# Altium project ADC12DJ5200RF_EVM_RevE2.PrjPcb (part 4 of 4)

## Sheet Power2_RevE2.SchDoc: EVM Power
size 431 x 279 mm; Date: Not shown in title block; ApprovedBy: Not shown in title block; CheckedBy: Not shown in title block; Author: Not shown in title block; CompanyName: Not shown in title block; DrawnBy: DWG; Engineer: DWG; Organization: Not shown in title block; Address1: Not shown in title block; Address2: Not shown in title block; Address3: Not shown in title block; Address4: Not shown in title block; DocumentNumber: 13; Revision: Use project parameter SCH_Rev; SheetNumber: 13; SheetTotal: 15; PageSetup: Record=PageOptions¦CenterHorizontal=True¦CenterVertical=True¦PrintScale=1.00¦XCorrection=1.00¦YCorrection=1.00¦PrintKind=0¦BorderSize=5000000¦LeftOffset=0¦BottomOffset=0¦Orientation=2¦PaperLength=1000¦PaperWidth=1000¦Scale=100¦PaperSource=15¦PrintQuality=600¦MediaType=1¦DitherType=10¦PaperKind=Letter¦PrintScaleMode=1
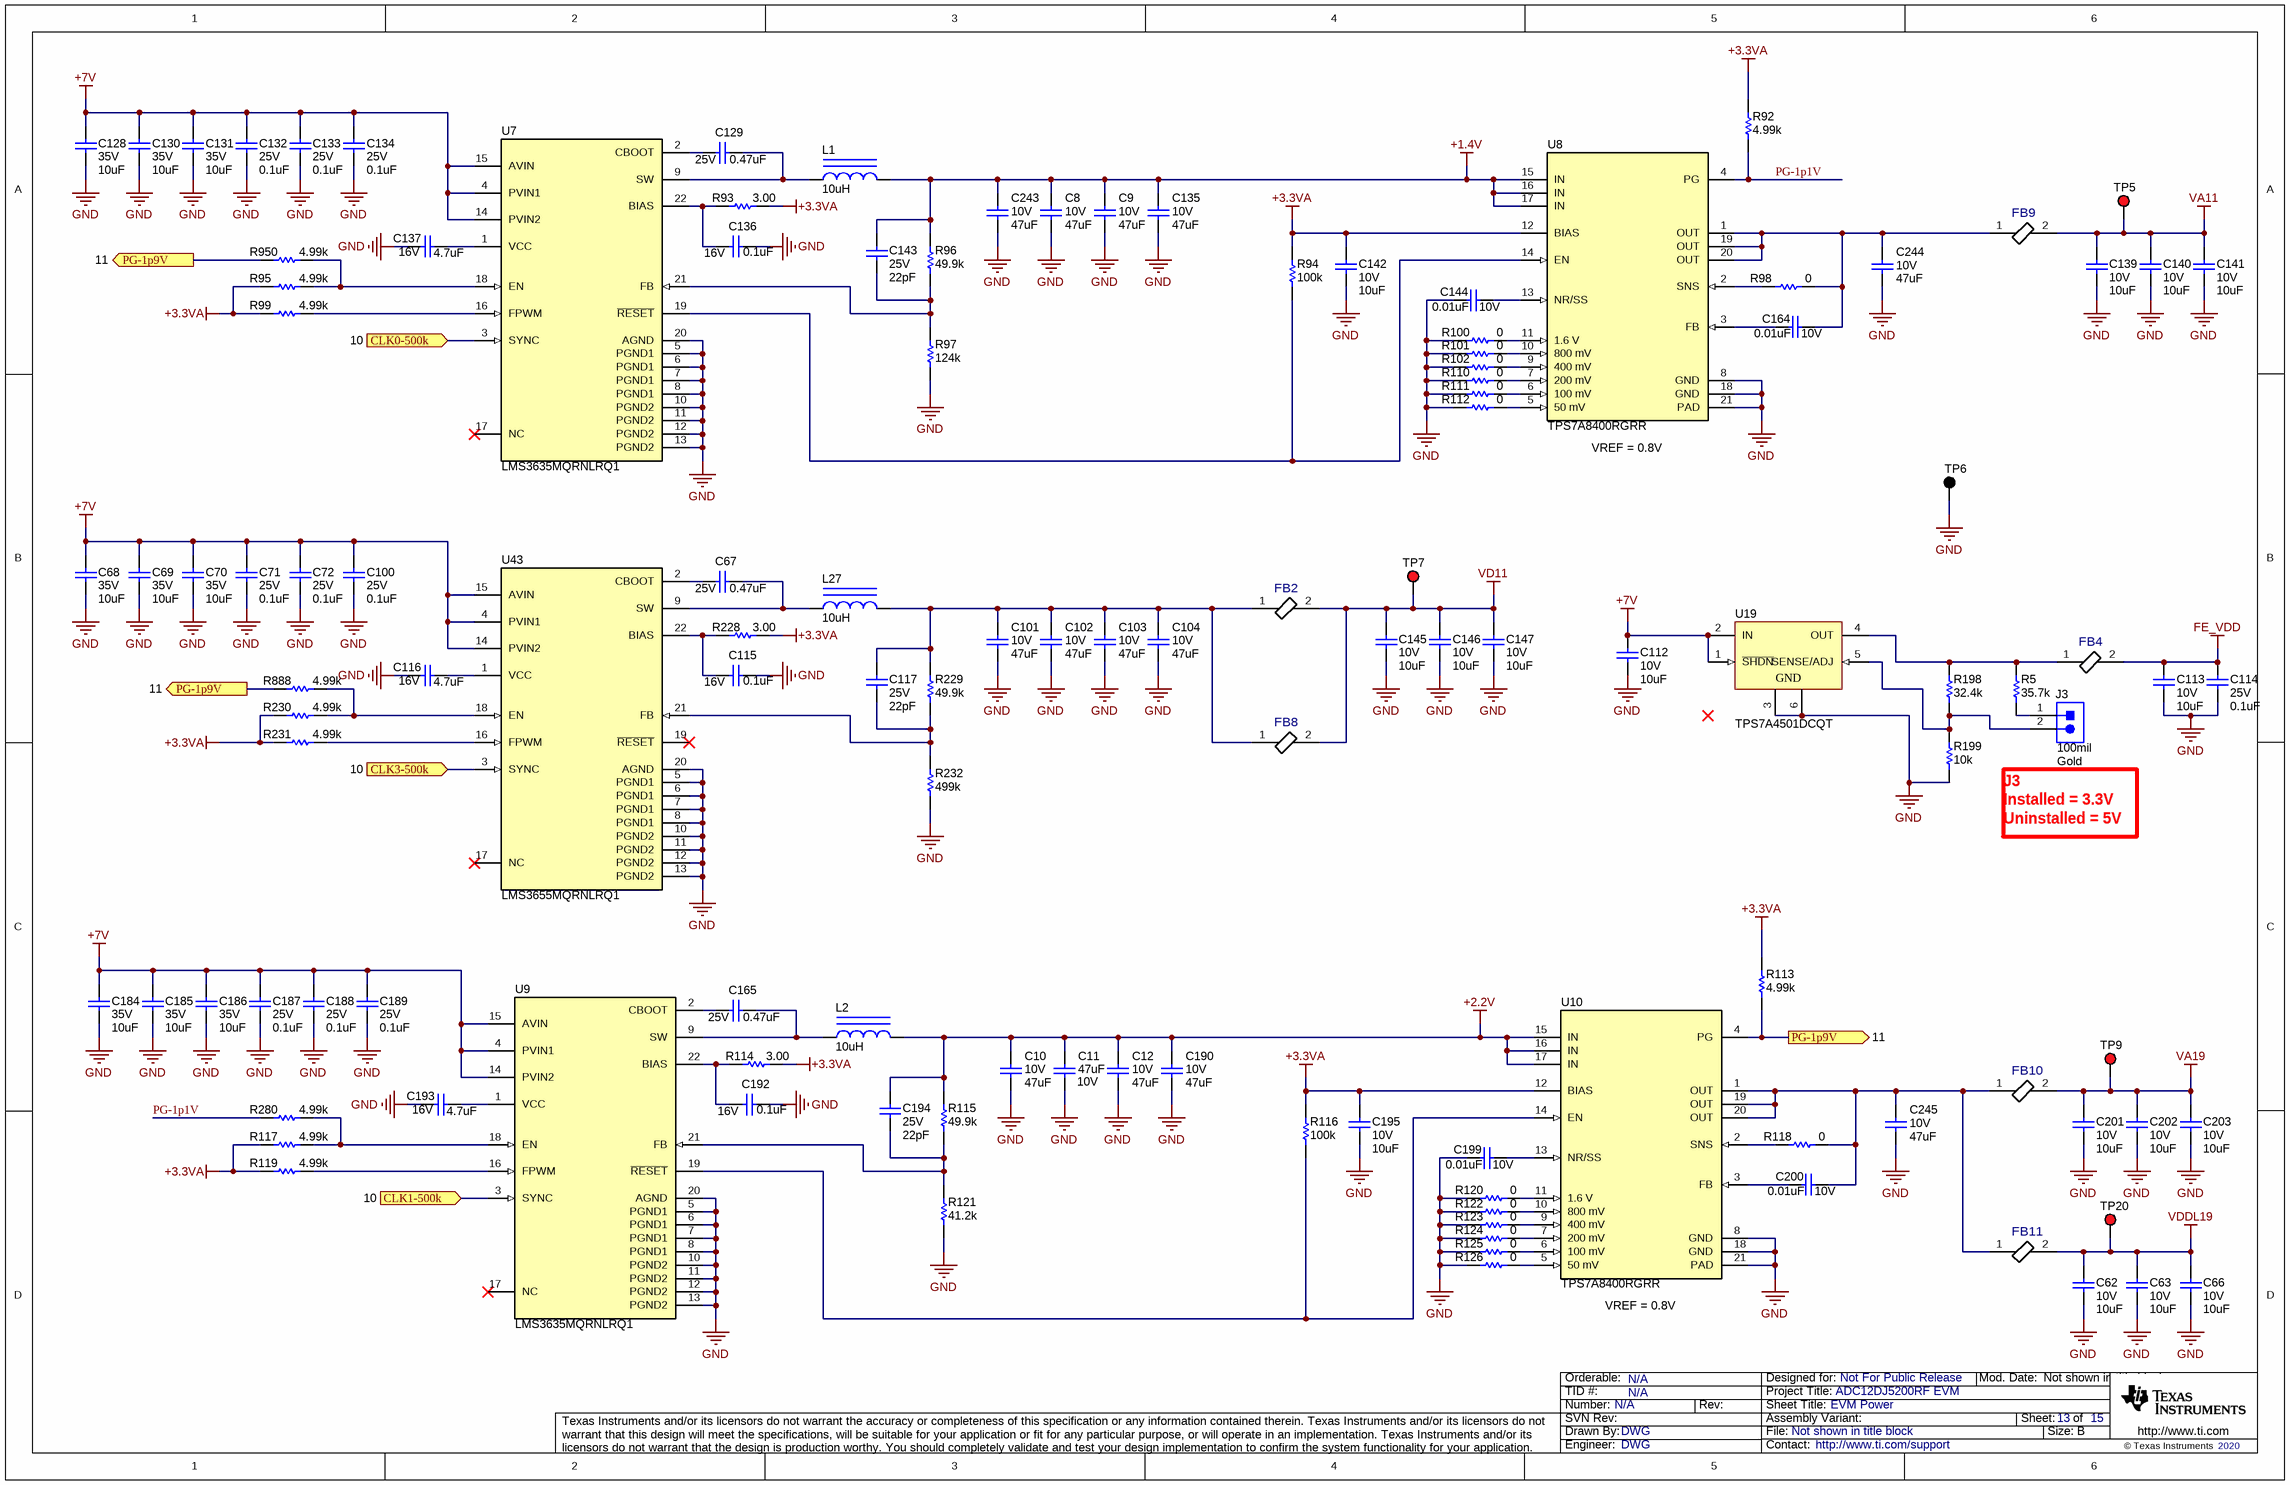
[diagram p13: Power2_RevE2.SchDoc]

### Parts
C8  VDC_V: 10V  ValueDisplayed: 47uF  [1210_270]  (hidden comment: GRM32ER71A476KE15L)
C9  VDC_V: 10V  ValueDisplayed: 47uF  [1210_270]  (hidden comment: GRM32ER71A476KE15L)
C10  VDC_V: 10V  ValueDisplayed: 47uF  [1210_270]  (hidden comment: GRM32ER71A476KE15L)
C11  VDC_V: 10V  ValueDisplayed: 47uF  [1210_270]  (hidden comment: GRM32ER71A476KE15L)
C12  VDC_V: 10V  ValueDisplayed: 47uF  [1210_270]  (hidden comment: GRM32ER71A476KE15L)
C62  VDC_V: 10V  ValueDisplayed: 10uF  [0603]  (hidden comment: GRM188Z71A106MA73D)
C63  VDC_V: 10V  ValueDisplayed: 10uF  [0603]  (hidden comment: GRM188Z71A106MA73D)
C66  VDC_V: 10V  ValueDisplayed: 10uF  [0603]  (hidden comment: GRM188Z71A106MA73D)
C67  VDC_V: 25V  ValueDisplayed: 0.47uF  [0603]  (hidden comment: GRM188R71E474KA12D)
C68  VDC_V: 35V  ValueDisplayed: 10uF  [1206_180]  (hidden comment: C3216X7R1V106K160AC)
C69  VDC_V: 35V  ValueDisplayed: 10uF  [1206_180]  (hidden comment: C3216X7R1V106K160AC)
C70  VDC_V: 35V  ValueDisplayed: 10uF  [1206_180]  (hidden comment: C3216X7R1V106K160AC)
C71  VDC_V: 25V  ValueDisplayed: 0.1uF  [0603]  (hidden comment: C1608X7R1E104K080AA)
C72  VDC_V: 25V  ValueDisplayed: 0.1uF  [0603]  (hidden comment: C1608X7R1E104K080AA)
C100  VDC_V: 25V  ValueDisplayed: 0.1uF  [0603]  (hidden comment: C1608X7R1E104K080AA)
C101  VDC_V: 10V  ValueDisplayed: 47uF  [1210_270]  (hidden comment: GRM32ER71A476KE15L)
C102  VDC_V: 10V  ValueDisplayed: 47uF  [1210_270]  (hidden comment: GRM32ER71A476KE15L)
C103  VDC_V: 10V  ValueDisplayed: 47uF  [1210_270]  (hidden comment: GRM32ER71A476KE15L)
C104  VDC_V: 10V  ValueDisplayed: 47uF  [1210_270]  (hidden comment: GRM32ER71A476KE15L)
C112  VDC_V: 10V  ValueDisplayed: 10uF  [0603]  (hidden comment: GRM188Z71A106MA73D)
C113  VDC_V: 10V  ValueDisplayed: 10uF  [0603]  (hidden comment: GRM188Z71A106MA73D)
C114  VDC_V: 25V  ValueDisplayed: 0.1uF  [0603]  (hidden comment: C1608X7R1E104K080AA)
C115  VDC_V: 16V  ValueDisplayed: 0.1uF  [0201]  (hidden comment: GRM033Z71C104KE14D)
C116  VDC_V: 16V  ValueDisplayed: 4.7uF  [0603]  (hidden comment: GRM188Z71C475KE21D)
C117  VDC_V: 25V  ValueDisplayed: 22pF  [0201_033]  (hidden comment: GCM0335C1E220JD03D)
C128  VDC_V: 35V  ValueDisplayed: 10uF  [1206_180]  (hidden comment: C3216X7R1V106K160AC)
C129  VDC_V: 25V  ValueDisplayed: 0.47uF  [0603]  (hidden comment: GRM188R71E474KA12D)
C130  VDC_V: 35V  ValueDisplayed: 10uF  [1206_180]  (hidden comment: C3216X7R1V106K160AC)
C131  VDC_V: 35V  ValueDisplayed: 10uF  [1206_180]  (hidden comment: C3216X7R1V106K160AC)
C132  VDC_V: 25V  ValueDisplayed: 0.1uF  [0603]  (hidden comment: C1608X7R1E104K080AA)
C133  VDC_V: 25V  ValueDisplayed: 0.1uF  [0603]  (hidden comment: C1608X7R1E104K080AA)
C134  VDC_V: 25V  ValueDisplayed: 0.1uF  [0603]  (hidden comment: C1608X7R1E104K080AA)
C135  VDC_V: 10V  ValueDisplayed: 47uF  [1210_270]  (hidden comment: GRM32ER71A476KE15L)
C136  VDC_V: 16V  ValueDisplayed: 0.1uF  [0201]  (hidden comment: GRM033Z71C104KE14D)
C137  VDC_V: 16V  ValueDisplayed: 4.7uF  [0603]  (hidden comment: GRM188Z71C475KE21D)
C139  VDC_V: 10V  ValueDisplayed: 10uF  [0603]  (hidden comment: GRM188Z71A106MA73D)
C140  VDC_V: 10V  ValueDisplayed: 10uF  [0603]  (hidden comment: GRM188Z71A106MA73D)
C141  VDC_V: 10V  ValueDisplayed: 10uF  [0603]  (hidden comment: GRM188Z71A106MA73D)
C142  VDC_V: 10V  ValueDisplayed: 10uF  [0603]  (hidden comment: GRM188Z71A106MA73D)
C143  VDC_V: 25V  ValueDisplayed: 22pF  [0201_033]  (hidden comment: GCM0335C1E220JD03D)
C144  VDC_V: 10V  ValueDisplayed: 0.01uF  [0201]  (hidden comment: GRM033R71A103KA01D)
C145  VDC_V: 10V  ValueDisplayed: 10uF  [0603]  (hidden comment: GRM188Z71A106MA73D)
C146  VDC_V: 10V  ValueDisplayed: 10uF  [0603]  (hidden comment: GRM188Z71A106MA73D)
C147  VDC_V: 10V  ValueDisplayed: 10uF  [0603]  (hidden comment: GRM188Z71A106MA73D)
C164  VDC_V: 10V  ValueDisplayed: 0.01uF  [0201]  (hidden comment: GRM033R71A103KA01D)
C165  VDC_V: 25V  ValueDisplayed: 0.47uF  [0603]  (hidden comment: GRM188R71E474KA12D)
C184  VDC_V: 35V  ValueDisplayed: 10uF  [1206_180]  (hidden comment: C3216X7R1V106K160AC)
C185  VDC_V: 35V  ValueDisplayed: 10uF  [1206_180]  (hidden comment: C3216X7R1V106K160AC)
C186  VDC_V: 35V  ValueDisplayed: 10uF  [1206_180]  (hidden comment: C3216X7R1V106K160AC)
C187  VDC_V: 25V  ValueDisplayed: 0.1uF  [0603]  (hidden comment: C1608X7R1E104K080AA)
C188  VDC_V: 25V  ValueDisplayed: 0.1uF  [0603]  (hidden comment: C1608X7R1E104K080AA)
C189  VDC_V: 25V  ValueDisplayed: 0.1uF  [0603]  (hidden comment: C1608X7R1E104K080AA)
C190  VDC_V: 10V  ValueDisplayed: 47uF  [1210_270]  (hidden comment: GRM32ER71A476KE15L)
C192  VDC_V: 16V  ValueDisplayed: 0.1uF  [0201]  (hidden comment: GRM033Z71C104KE14D)
C193  VDC_V: 16V  ValueDisplayed: 4.7uF  [0603]  (hidden comment: GRM188Z71C475KE21D)
C194  VDC_V: 25V  ValueDisplayed: 22pF  [0201_033]  (hidden comment: GCM0335C1E220JD03D)
C195  VDC_V: 10V  ValueDisplayed: 10uF  [0603]  (hidden comment: GRM188Z71A106MA73D)
C199  VDC_V: 10V  ValueDisplayed: 0.01uF  [0201]  (hidden comment: GRM033R71A103KA01D)
C200  VDC_V: 10V  ValueDisplayed: 0.01uF  [0201]  (hidden comment: GRM033R71A103KA01D)
C201  VDC_V: 10V  ValueDisplayed: 10uF  [0603]  (hidden comment: GRM188Z71A106MA73D)
C202  VDC_V: 10V  ValueDisplayed: 10uF  [0603]  (hidden comment: GRM188Z71A106MA73D)
C203  VDC_V: 10V  ValueDisplayed: 10uF  [0603]  (hidden comment: GRM188Z71A106MA73D)
C243  VDC_V: 10V  ValueDisplayed: 47uF  [1210_270]  (hidden comment: GRM32ER71A476KE15L)
C244  VDC_V: 10V  ValueDisplayed: 47uF  [1210_270]  (hidden comment: GRM32ER71A476KE15L)
C245  VDC_V: 10V  ValueDisplayed: 47uF  [1210_270]  (hidden comment: GRM32ER71A476KE15L)
FB2  BLM21SN300SN1D  [FP-BLM21SN300SN1D_0805-MFG]  (value not drawn)
FB4  BLM21SN300SN1D  [FP-BLM21SN300SN1D_0805-MFG]  (value not drawn)
FB8  BLM21SN300SN1D  [FP-BLM21SN300SN1D_0805-MFG]  (value not drawn)
FB9  BLM21SN300SN1D  [FP-BLM21SN300SN1D_0805-MFG]  (value not drawn)
FB10  BLM21SN300SN1D  [FP-BLM21SN300SN1D_0805-MFG]  (value not drawn)
FB11  BLM21SN300SN1D  [FP-BLM21SN300SN1D_0805-MFG]  (value not drawn)
J3  Pitch_mm: 100mil  ContactFinish: Gold  [Molex_0022284023]  (hidden comment: 3p3V)
L1  ValueDisplayed: 10uH  [XAL8080]  (hidden comment: XAL8080-103MEB)
L2  ValueDisplayed: 10uH  [XAL8080]  (hidden comment: XAL8080-103MEB)
L27  ValueDisplayed: 10uH  [XAL8080]  (hidden comment: XAL8080-103MEB)
R5  ValueDisplayed: 35.7k  [0603]  (hidden comment: RC0603FR-0735K7L)
R92  ValueDisplayed: 4.99k  [0201]  (hidden comment: RC0201FS-7D4K99L)
R93  ValueDisplayed: 3.00  [0201]  (hidden comment: RC0201FR-073RL)
R94  ValueDisplayed: 100k  [0201]  (hidden comment: RC0201FS-7D4K99L)
R95  ValueDisplayed: 4.99k  [0201]  (hidden comment: RC0201FS-7D4K99L)
R96  ValueDisplayed: 49.9k  [0201]  (hidden comment: RC0201FR-7D49K9L)
R97  ValueDisplayed: 124k  [0201]  (hidden comment: RC0201FR-7D124KL)
R98  ValueDisplayed: 0  [0201]  (hidden comment: CRCW02010000Z0ED)
R99  ValueDisplayed: 4.99k  [0201]  (hidden comment: RC0201FS-7D4K99L)
R100  ValueDisplayed: 0  [0201]  (hidden comment: CRCW02010000Z0ED)
R101  ValueDisplayed: 0  [0201]  (hidden comment: CRCW02010000Z0ED)
R102  ValueDisplayed: 0  [0201]  (hidden comment: CRCW02010000Z0ED)
R110  ValueDisplayed: 0  [0201]  (hidden comment: CRCW02010000Z0ED)
R111  ValueDisplayed: 0  [0201]  (hidden comment: CRCW02010000Z0ED)
R112  ValueDisplayed: 0  [0201]  (hidden comment: CRCW02010000Z0ED)
R113  ValueDisplayed: 4.99k  [0201]  (hidden comment: RC0201FS-7D4K99L)
R114  ValueDisplayed: 3.00  [0201]  (hidden comment: RC0201FR-073RL)
R115  ValueDisplayed: 49.9k  [0201]  (hidden comment: RC0201FR-7D49K9L)
R116  ValueDisplayed: 100k  [0201]  (hidden comment: RC0201FS-7D4K99L)
R117  ValueDisplayed: 4.99k  [0201]  (hidden comment: RC0201FS-7D4K99L)
R118  ValueDisplayed: 0  [0201]  (hidden comment: CRCW02010000Z0ED)
R119  ValueDisplayed: 4.99k  [0201]  (hidden comment: RC0201FS-7D4K99L)
R120  ValueDisplayed: 0  [0201]  (hidden comment: CRCW02010000Z0ED)
R121  ValueDisplayed: 41.2k  [0201]  (hidden comment: RC0201FR-0741K2L)
R122  ValueDisplayed: 0  [0201]  (hidden comment: CRCW02010000Z0ED)
R123  ValueDisplayed: 0  [0201]  (hidden comment: CRCW02010000Z0ED)
R124  ValueDisplayed: 0  [0201]  (hidden comment: CRCW02010000Z0ED)
R125  ValueDisplayed: 0  [0201]  (hidden comment: CRCW02010000Z0ED)
R126  ValueDisplayed: 0  [0201]  (hidden comment: CRCW02010000Z0ED)
R198  ValueDisplayed: 32.4k  [0603]  (hidden comment: RC0603FR-0732K4L)
R199  ValueDisplayed: 10k  [0603]  (hidden comment: RC0603JR-0710KL)
R228  ValueDisplayed: 3.00  [0201]  (hidden comment: RC0201FR-073RL)
R229  ValueDisplayed: 49.9k  [0201]  (hidden comment: RC0201FR-7D49K9L)
R230  ValueDisplayed: 4.99k  [0201]  (hidden comment: RC0201FS-7D4K99L)
R231  ValueDisplayed: 4.99k  [0201]  (hidden comment: RC0201FS-7D4K99L)
R232  ValueDisplayed: 499k  [0201L]  (hidden comment: RC0201FR-07499KL)
R280  ValueDisplayed: 4.99k  [0201]  (hidden comment: RC0201FS-7D4K99L)
R888  ValueDisplayed: 4.99k  [0201]  (hidden comment: RC0201FS-7D4K99L)
R950  ValueDisplayed: 4.99k  [0201]  (hidden comment: RC0201FS-7D4K99L)
TP5  5000  [Keystone5000]  (value not drawn)
TP6  5001  [Keystone5001]  (value not drawn)
TP7  5000  [Keystone5000]  (value not drawn)
TP9  5000  [Keystone5000]  (value not drawn)
TP20  5000  [Keystone5000]  (value not drawn)
U7  LMS3635MQRNLRQ1  [RNL0022A]
U8  TPS7A8400RGRR  [RGR0020A]
U9  LMS3635MQRNLRQ1  [RNL0022A]
U10  TPS7A8400RGRR  [RGR0020A]
U19  TPS7A4501DCQT  [DCQ0006A_N]
U43  LMS3655MQRNLRQ1  [RNL0022A]

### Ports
CLK0-500k (in, see 10), CLK1-500k (in, see 10), CLK3-500k (in, see 10), PG-1p9V (out, see 11)

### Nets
+1.4V: C8.1 C9.1 C135.1 C143.1 C243.1 L1.2 R96.2 U8.15(IN) U8.16(IN) U8.17(IN)
+2.2V: C10.1 C11.1 C12.1 C190.1 C194.1 L2.2 R115.2 U10.15(IN) U10.16(IN) U10.17(IN)
+3.3VA: C142.1 C195.1 R92.1 R93.2 R94.1 R95.2 R99.2 R113.1 R114.2 R116.1 R117.2 R119.2 R228.2 R230.2 R231.2 U8.12(BIAS) U10.12(BIAS)
+7V: C68.1 C69.1 C70.1 C71.1 C72.1 C100.1 C112.1 C128.1 C130.1 C131.1 C132.1 C133.1 C134.1 C184.1 C185.1 C186.1 C187.1 C188.1 C189.1 U7.4(PVIN1) U7.14(PVIN2) U7.15(AVIN) U9.4(PVIN1) U9.14(PVIN2) U9.15(AVIN) U19.1(~{SHDN}) U19.2(IN) U43.4(PVIN1) U43.14(PVIN2) U43.15(AVIN)
FE_VDD: C113.1 C114.1 FB4.2
GND: C8.2 C9.2 C10.2 C11.2 C12.2 C62.2 C63.2 C66.2 C68.2 C69.2 C70.2 C71.2 C72.2 C100.2 C101.2 C102.2 C103.2 C104.2 C112.2 C113.2 C114.2 C115.1 C116.1 C128.2 C130.2 C131.2 C132.2 C133.2 C134.2 C135.2 C136.1 C137.1 C139.2 C140.2 C141.2 C142.2 C144.2 C145.2 C146.2 C147.2 C184.2 C185.2 C186.2 C187.2 C188.2 C189.2 C190.2 C192.1 C193.1 C195.2 C199.2 C201.2 C202.2 C203.2 C243.2 C244.2 C245.2 R97.1 R100.1 R101.1 R102.1 R110.1 R111.1 R112.1 R120.1 R121.1 R122.1 R123.1 R124.1 R125.1 R126.1 R199.1 R232.1 TP6.1 U7.5(PGND1) U7.6(PGND1) U7.7(PGND1) U7.8(PGND1) U7.10(PGND2) U7.11(PGND2) U7.12(PGND2) U7.13(PGND2) U7.20(AGND) U8.8(GND) U8.18(GND) U8.21(PAD) U9.5(PGND1) U9.6(PGND1) U9.7(PGND1) U9.8(PGND1) U9.10(PGND2) U9.11(PGND2) U9.12(PGND2) U9.13(PGND2) U9.20(AGND) U10.8(GND) U10.18(GND) U10.21(PAD) U19.3(GND) U19.6(GND) U43.5(PGND1) U43.6(PGND1) U43.7(PGND1) U43.8(PGND1) U43.10(PGND2) U43.11(PGND2) U43.12(PGND2) U43.13(PGND2) U43.20(AGND)
VA11: C139.1 C140.1 C141.1 FB9.2 TP5.1
VA19: C201.1 C202.1 C203.1 FB10.2 TP9.1
VD11: C145.1 C146.1 C147.1 FB2.2 FB8.2 TP7.1
VDDL19: C62.1 C63.1 C66.1 FB11.2 TP20.1
CLK0-500k: U7.3(SYNC) ; port CLK0-500k
CLK1-500k: U9.3(SYNC) ; port CLK1-500k
CLK3-500k: U43.3(SYNC) ; port CLK3-500k
PG-1p1V: R92.2 R280.2 U8.4(PG)
PG-1p9V: R113.2 R888.2 R950.2 U10.4(PG) ; port PG-1p9V
NetC67_1: C67.1 U43.2(CBOOT)
NetC67_2: C67.2 L27.1 U43.9(SW)
NetC101_1: C101.1 C102.1 C103.1 C104.1 C117.1 FB2.1 FB8.1 L27.2 R229.2
NetC115_2: C115.2 R228.1 U43.22(BIAS)
NetC116_2: C116.2 U43.1(VCC)
NetC117_2: C117.2 R229.1 R232.2 U43.21(FB)
NetC129_1: C129.1 U7.2(CBOOT)
NetC129_2: C129.2 L1.1 U7.9(SW)
NetC136_2: C136.2 R93.1 U7.22(BIAS)
NetC137_2: C137.2 U7.1(VCC)
NetC143_2: C143.2 R96.1 R97.2 U7.21(FB)
NetC144_1: C144.1 U8.13(NR/SS)
NetC164_1: C164.1 C244.1 FB9.1 R98.2 U8.1(OUT) U8.19(OUT) U8.20(OUT)
NetC164_2: C164.2 U8.3(FB)
NetC165_1: C165.1 U9.2(CBOOT)
NetC165_2: C165.2 L2.1 U9.9(SW)
NetC192_2: C192.2 R114.1 U9.22(BIAS)
NetC193_2: C193.2 U9.1(VCC)
NetC194_2: C194.2 R115.1 R121.2 U9.21(FB)
NetC199_1: C199.1 U10.13(NR/SS)
NetC200_1: C200.1 C245.1 FB10.1 FB11.1 R118.2 U10.1(OUT) U10.19(OUT) U10.20(OUT)
NetC200_2: C200.2 U10.3(FB)
NetFB4_1: FB4.1 R5.2 R198.2 U19.4(OUT)
NetJ3_1: J3.1 R5.1
NetJ3_2: J3.2 R198.1 R199.2 U19.5(SENSE/ADJ)
NetR94_2: R94.2 U7.19(~{RESET}) U8.14(EN)
NetR95_1: R95.1 R950.1 U7.18(EN)
NetR98_1: R98.1 U8.2(SNS)
NetR99_1: R99.1 U7.16(FPWM)
NetR100_2: R100.2 U8.11(1.6_V)
NetR101_2: R101.2 U8.10(800_mV)
NetR102_2: R102.2 U8.9(400_mV)
NetR110_2: R110.2 U8.7(200_mV)
NetR111_2: R111.2 U8.6(100_mV)
NetR112_2: R112.2 U8.5(50_mV)
NetR116_2: R116.2 U9.19(~{RESET}) U10.14(EN)
NetR117_1: R117.1 R280.1 U9.18(EN)
NetR118_1: R118.1 U10.2(SNS)
NetR119_1: R119.1 U9.16(FPWM)
NetR120_2: R120.2 U10.11(1.6_V)
NetR122_2: R122.2 U10.10(800_mV)
NetR123_2: R123.2 U10.9(400_mV)
NetR124_2: R124.2 U10.7(200_mV)
NetR125_2: R125.2 U10.6(100_mV)
NetR126_2: R126.2 U10.5(50_mV)
NetR230_1: R230.1 R888.1 U43.18(EN)
NetR231_1: R231.1 U43.16(FPWM)

Not connected (* = marked no-connect by the designer): U7 17(NC)*; U9 17(NC)*; U43 17(NC)* 19(~{RESET})*

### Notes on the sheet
- (near U8) VREF = 0.8V
- J3
  Installed = 3.3V
  Uninstalled = 5V
- (near U10) VREF = 0.8V

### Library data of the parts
C8-C12 C101-C104 C135 C190 C243-C245 = CMP-0009220-2: CAP, CERM, 47 uF, 10 V, +/- 10%, X7R, 1210; Manufacturer: MuRata; TaMin_C: -55°C; Polarized: N; SizeAreaWB_mm2: 14.7; Value1: Unknown; U/M: EA; Value: 47uF; TaMax_C: 125°C; SizeZ_mm: 2.7; SizeX_mm: 3.2; SizeY_mm: 2.5; Cap_Case: 1210; SizeArea_mm2: 8; Cap_F: 47µF; AEC Category: Q200
C62 C63 C66 C112 C113 C139-C142 C145-C147 C195 C201-C203 = CMP-0007497-5: CAP, CERM, 10 uF, 10 V, +/- 20%, X7R, 0603; Manufacturer: MuRata; TaMin_C: -55°C; Polarized: N; SizeAreaWB_mm2: 4.68; Value1: Unknown; U/M: EA; Value: 10uF; TaMax_C: 125°C; SizeZ_mm: 1; SizeX_mm: 1.6; SizeY_mm: 0.8; SizeArea_mm2: 1.28; Cap_F: 10µF; AEC Category: Q200
C67 C129 C165 = CMP-0007424-4: CAP, CERM, 0.47 uF, 25 V, +/- 10%, X7R, 0603; Manufacturer: MuRata; TaMin_C: -55°C; Polarized: N; SizeAreaWB_mm2: 4.68; Value1: Unknown; U/M: EA; Value: 0.47uF; TaMax_C: 125°C; SizeZ_mm: 1; SizeX_mm: 1.6; SizeY_mm: 0.8; SizeArea_mm2: 1.28; Cap_F: 470nF; AEC Category: Q200
C68-C70 C128 C130 C131 C184-C186 = CMP-0008705-2: CAP, CERM, 10 uF, 35 V, +/- 10%, X7R, 1206; Manufacturer: TDK; TaMin_C: -55°C; ESR_ohm: 2.229m; Polarized: N; SizeAreaWB_mm2: 10.92; Value1: 0.002229 ohm; U/M: EA; Value: 10uF; TaMax_C: 125°C; SizeZ_mm: 1.8; SizeX_mm: 3.2; SizeY_mm: 1.6; SizeArea_mm2: 5.12; Cap_F: 10µF; IRMS_A: 4.85932A; AEC Category: Q200
C71 C72 C100 C114 C132-C134 C187-C189 = CMP-0007039-5: CAP, CERM, 0.1 uF, 25 V, +/- 10%, X7R, 0603; Manufacturer: TDK; TaMin_C: -55°C; Polarized: N; SizeAreaWB_mm2: 4.68; Value1: Unknown; U/M: EA; Value: 0.1uF; TaMax_C: 125°C; SizeZ_mm: 1; SizeX_mm: 1.6; SizeY_mm: 0.8; SizeArea_mm2: 1.28; Cap_F: 100nF; AEC Category: Q200
C115 C136 C192 = CMP-0064970-1: CAP, CERM, 0.1 uF, 16 V,+/- 10%, X7R, 0201; Manufacturer: MuRata; TaMin_C: -55°C; Polarized: N; SizeAreaWB_mm2: 2.08; Value1: Unknown; U/M: EA; Value: 0.1uF; TaMax_C: 125°C; SizeZ_mm: 0.26; SizeX_mm: 0.6; SizeY_mm: 0.3; SizeArea_mm2: 0.18; Cap_F: 100nF; AEC Category: Q200
C116 C137 C193 = CMP-0064936-4: CAP, CERM, 4.7 uF, 16 V,+/- 10%, X7R, 0603; Manufacturer: MuRata; TaMin_C: -55°C; Polarized: N; SizeAreaWB_mm2: 4.68; Value1: Unknown; U/M: EA; Value: 4.7uF; TaMax_C: 125°C; SizeZ_mm: 1; SizeX_mm: 1.6; SizeY_mm: 0.8; SizeArea_mm2: 1.28; Cap_F: 4.7µF; AEC Category: Q200
C117 C143 C194 = CMP-0009659-3: CAP, CERM, 22 pF, 25 V, +/- 5%, C0G/NP0, AEC-Q200 Grade 1, 0201; Manufacturer: MuRata; TaMin_C: -55°C; Polarized: N; SizeAreaWB_mm2: 2.08; Value1: Unknown; U/M: EA; Value: 22pF; TaMax_C: 125°C; SizeZ_mm: 0.33; SizeX_mm: 0.6; SizeY_mm: 0.3; Cap_Case: 0201; SizeArea_mm2: 0.18; AEC Qualified: Y; AEC Grade: 1; AEC Category: Q200
C144 C164 C199 C200 = CMP-0009732-1: CAP, CERM, 0.01 uF, 10 V, +/- 10%, X7R, 0201; Manufacturer: MuRata; TaMin_C: -55°C; Polarized: N; SizeAreaWB_mm2: 2.08; Value1: Unknown; U/M: EA; Value: 0.01uF; TaMax_C: 125°C; SizeZ_mm: 0.26; SizeX_mm: 0.6; SizeY_mm: 0.3; SizeArea_mm2: 0.18; Cap_F: 10nF; AEC Category: Q200
FB2 FB4 FB8-FB11 = CMP-0081829-1: 30 Ohms @ 100MHz 1 Power Line Ferrite Bead 0805 (2012 Metric) 8.5A 4mOhm; Manufacturer: Murata; SizeZ_mm: 1.05mm; Impedance At Frequency: 30Ω @ 100MHz; Symbol Name: SYM-BLM21SN300SN1D; AEC Qualified: No; DCR_ohm: 0.004Ω
J3 = CMP-0055333-1: Header, 2.54mm, 2x1, Tin, TH; Manufacturer: Molex; PartNumber: 22284023; CNHeader: TRUE; Current_A: 4A; Shrouded: N; Gender: Male; Voltage_V: 250V; Row_Count: 1; CT: FALSE; Cert_UL: Y
L1 L2 L27 = CMP-0061060-1: Inductor, Shielded, Composite, 10 uH, 8.7 A, 0.021 ohm, SMD; Manufacturer: Coilcraft; Isat: 11A @ 30% inductance drop; Irms: 8.7A @ 40C rise; Green_Lifecycle: Not Set; SizeAreaWB_mm2: 107.06; DCR_ohm: 0.021; Green_REACh: Incomplete; Value: 10uH; Imax_A: 8.7A; SizeZ_mm: 8; SizeX_mm: 8.1; SizeY_mm: 8.6; SizeArea_mm2: 69.66; Ind_H: 10µH; AEC Qualified: N; AEC Category: Q200
R5 = CMP-0023050-5: RES, 35.7 k, 1%, 0.1 W, 0603; Manufacturer: Yageo; Power_W: 100mW; TempCo: 100 ppm/C; Value_Code: 35k7; Value: 35.7k; EIA_Code: E96; SizeX_mm: 1.6; SizeY_mm: 0.8; SizeZ_mm: 1; Value2: 0.1W; SizeArea_mm2: 1.28; AEC Qualified: N; VDC_V: 75V; AEC Category: Q200; SizeAreaWB_mm2: 4.68
R92 R95 R99 R113 R117 R119 R230 R231 R280 = CMP-0028107-1: RES, 4.99 k, 1%, 0.05 W, 0201; Manufacturer: Yageo America; Power_W: 50mW; TempCo: 200 ppm/C; Value_Code: 4k99; U/M: EA; Value: 4.99k; EIA_Code: E96; SizeX_mm: 0.6; SizeY_mm: 0.3; SizeZ_mm: 0.26; Value2: 0.05W; SizeArea_mm2: 0.18; AEC Qualified: N; VDC_V: 25V; AEC Category: Q200
R93 R114 R228 = CMP-0027685-1: RES, 3.00, 1%, 0.05 W, 0201; Manufacturer: Yageo America; Power_W: 50mW; TempCo: 350 ppm/C; Value_Code: 3R00; U/M: EA; Value: 3.00; Res_ohm: 3; SizeX_mm: 0.6; SizeY_mm: 0.3; SizeZ_mm: 0.26; Value2: 0.05W; SizeArea_mm2: 0.18; AEC Qualified: N; VDC_V: 25V; AEC Category: Q200
R94 R116 = CMP-0028069-1: RES, 100 k, 1%, 0.05 W, 0201; Manufacturer: Yageo America; PartNumber: RC0201FS-7D100KL; Power_W: 50mW; TempCo: 200 ppm/C; U/M: EA; Value: 100k; EIA_Code: E96; SizeX_mm: 0.6; SizeY_mm: 0.3; SizeZ_mm: 0.26; Value2: 0.05W; SizeArea_mm2: 0.18; CompType: Resistor; AEC Qualified: N; VDC_V: 25V; AEC Category: Q200
R96 R115 R229 = CMP-0028027-1: RES, 49.9 k, 1%, 0.05 W, 0201; Manufacturer: Yageo America; Power_W: 50mW; TempCo: 200 ppm/C; Value_Code: 49k9; U/M: EA; Value: 49.9k; EIA_Code: E96; SizeX_mm: 0.6; SizeY_mm: 0.3; SizeZ_mm: 0.26; Value2: 0.05W; SizeArea_mm2: 0.18; AEC Qualified: N; VDC_V: 25V; AEC Category: Q200
R97 = CMP-0027952-1: RES, 124 k, 1%, 0.05 W, 0201; Manufacturer: Yageo America; Power_W: 50mW; TempCo: 200 ppm/C; U/M: EA; Value: 124k; EIA_Code: E96; SizeX_mm: 0.6; SizeY_mm: 0.3; SizeZ_mm: 0.26; Value2: 0.05W; SizeArea_mm2: 0.18; AEC Qualified: N; VDC_V: 25V; AEC Category: Q200
R98 R100-R102 R110-R112 R118 R120 R122-R126 = CMP-0027008-4: RES, 0, 5%, 0.05 W, 0201; Manufacturer: Vishay-Dale; Power_W: 50mW; TempCo: ppm/C; Value_Code: 0000; Value: 0; EIA_Code: E24; SizeX_mm: 0.6; SizeY_mm: 0.3; SizeZ_mm: 0.26; Value2: 0.05W; SizeArea_mm2: 0.18; AEC Qualified: N; AEC Category: Q200
R121 = CMP-0027692-1: RES, 41.2 k, 1%, 0.05 W, 0201; Manufacturer: Yageo America; Power_W: 50mW; TempCo: 200 ppm/C; Value_Code: 41k2; U/M: EA; Value: 41.2k; EIA_Code: E96; SizeX_mm: 0.6; SizeY_mm: 0.3; SizeZ_mm: 0.26; Value2: 0.05W; SizeArea_mm2: 0.18; CompType: Resistor; AEC Qualified: N; VDC_V: 25V; AEC Category: Q200
R198 = CMP-0023030-5: RES, 32.4 k, 1%, 0.1 W, 0603; Manufacturer: Yageo; Power_W: 100mW; TempCo: 100 ppm/C; Value_Code: 32k4; Value: 32.4k; EIA_Code: E96; SizeX_mm: 1.6; SizeY_mm: 0.8; SizeZ_mm: 1; Value2: 0.1W; SizeArea_mm2: 1.28; AEC Qualified: N; VDC_V: 75V; AEC Category: Q200; SizeAreaWB_mm2: 4.68
R199 = CMP-0025886-5: RES, 10 k, 5%, 0.1 W, 0603; Manufacturer: Yageo; Power_W: 100mW; TempCo: 100 ppm/C; Value_Code: 10k0; Value: 10k; EIA_Code: E24; SizeX_mm: 1.6; SizeY_mm: 0.8; SizeZ_mm: 1; Value2: 0.1W; SizeArea_mm2: 1.28; AEC Qualified: N; VDC_V: 75V; AEC Category: Q200; SizeAreaWB_mm2: 4.68
R232 = CMP-0027730-1: RES, 499 k, 1%, 0.05 W, 0201; Manufacturer: Yageo America; Power_W: 50mW; TempCo: 200 ppm/C; U/M: EA; Value: 499k; EIA_Code: E96; SizeX_mm: 0.6; SizeY_mm: 0.3; SizeZ_mm: 0.26; Value2: 0.05W; SizeArea_mm2: 0.18; AEC Qualified: N; VDC_V: 25V; AEC Category: Q200
R888 R950 = CMP-0028107-1: RES, 4.99 k, 1%, 0.05 W, 0201; Manufacturer: Yageo America; Power_W: 50mW; TempCo: 200 ppm/C; Value_Code: 4k99; U/M: EA; Value: 4.99k; EIA_Code: E96; SizeX_mm: 0.6; SizeY_mm: 0.3; SizeZ_mm: 0.26; Value2: 0.05W; SizeArea_mm2: 0.18; CompType: Resistor; AEC Qualified: N; VDC_V: 25V; AEC Category: Q200
TP5 TP7 TP9 TP20 = CMP-0055137-1: Test Point, Miniature, Red, TH; Manufacturer: Keystone; CNHeader: FALSE; Green_Lifecycle: Active; Green_REACh: Passed; ContactFinish: Silver; CT: TRUE
TP6 = CMP-0055138-1: Test Point, Miniature, Black, TH; Manufacturer: Keystone; CNHeader: FALSE; Green_Lifecycle: Active; Green_REACh: Passed; ContactFinish: Silver; CT: TRUE
U7 U9 = CMP-0013906-5: 3.5A, 36V Synchronous, 400kHz, Step-Down Converter, RNL0022A (VQFN-HR-22); Manufacturer: Texas Instruments; Alternate PartNumber: LMS3635MQRNLTQ1; SizeX_mm: 4.0; SizeY_mm: 5.0; CompType: IC; SizeZ_mm: 0.9; SizeArea_mm2: 20.0; SizeAreaWB_mm2: 42.0; AEC Category: Q200; AEC Qualified: Y; Rating: Automotive
U8 U10 = CMP-0073871-3: High-Current (3 A), High-Accuracy (1%), Low-Noise (4.4 uVRMS), LDO Voltage Regulator, RGR0020A (VQFN-20); Alternate PartNumber: TPS7A8400RGRT; Alternate Manufacturer: Texas Instruments; Green_Lifecycle: Active; SizeAreaWB_mm2: 20.25; Green_REACh: Passed; SizeZ_mm: 1.0; SizeX_mm: 3.5; SizeArea_mm2: 12.25; CompType: IC; AEC Category: Q200; AEC Qualified: N
U19 = CMP-0036724-1: Single Output Fast Transient Response LDO, 1.5 A,Adjustable Output, 2.1 to 20 V Input, 6-pin SOT-223 (DCQ), -40 to 125 degC, Green (RoHS & no Sb/Br); Manufacturer: Texas Instruments; Vout Adj(Min)(V): 1.2; SubFamily: Single Channel LDO; Vdo(Typ)(mV): 300; Vin(Min)(V): 2.1; Accuracy(%): 1; Vin(Max)(V): 20; Vout Adj(Max)(V): 5; Iout(Max)(A): 1.5
U43 = CMP-0013911-5: 5.5A, 36V Synchronous, 400kHz, Step-Down Converter, RNL0022A (VQFN-HR-22); Manufacturer: Texas Instruments; Alternate PartNumber: LMS3655MQRNLTQ1; SizeX_mm: 4.0; SizeY_mm: 5.0; CompType: IC; SizeZ_mm: 0.9; SizeArea_mm2: 20.0; SizeAreaWB_mm2: 42.0; AEC Category: Q200; AEC Qualified: Y; Rating: Automotive

## Sheet USB_RevE2.SchDoc: USB Interface
size 431 x 279 mm; Date: Not shown in title block; ApprovedBy: Not shown in title block; CheckedBy: Not shown in title block; Author: Not shown in title block; CompanyName: Not shown in title block; DrawnBy: DWG; Engineer: Not shown in title block; Organization: Not shown in title block; Address1: Not shown in title block; Address2: Not shown in title block; Address3: Not shown in title block; Address4: Not shown in title block; DocumentNumber: 14; Revision: Use project parameter SCH_Rev; SheetNumber: 14; SheetTotal: 15; PageSetup: Record=PageOptions¦CenterHorizontal=True¦CenterVertical=True¦PrintScale=1.00¦XCorrection=1.00¦YCorrection=1.00¦PrintKind=0¦BorderSize=5000000¦LeftOffset=0¦BottomOffset=0¦Orientation=2¦PaperLength=1000¦PaperWidth=1000¦Scale=100¦PaperSource=15¦PrintQuality=600¦MediaType=1¦DitherType=10¦PaperKind=Letter¦PrintScaleMode=1
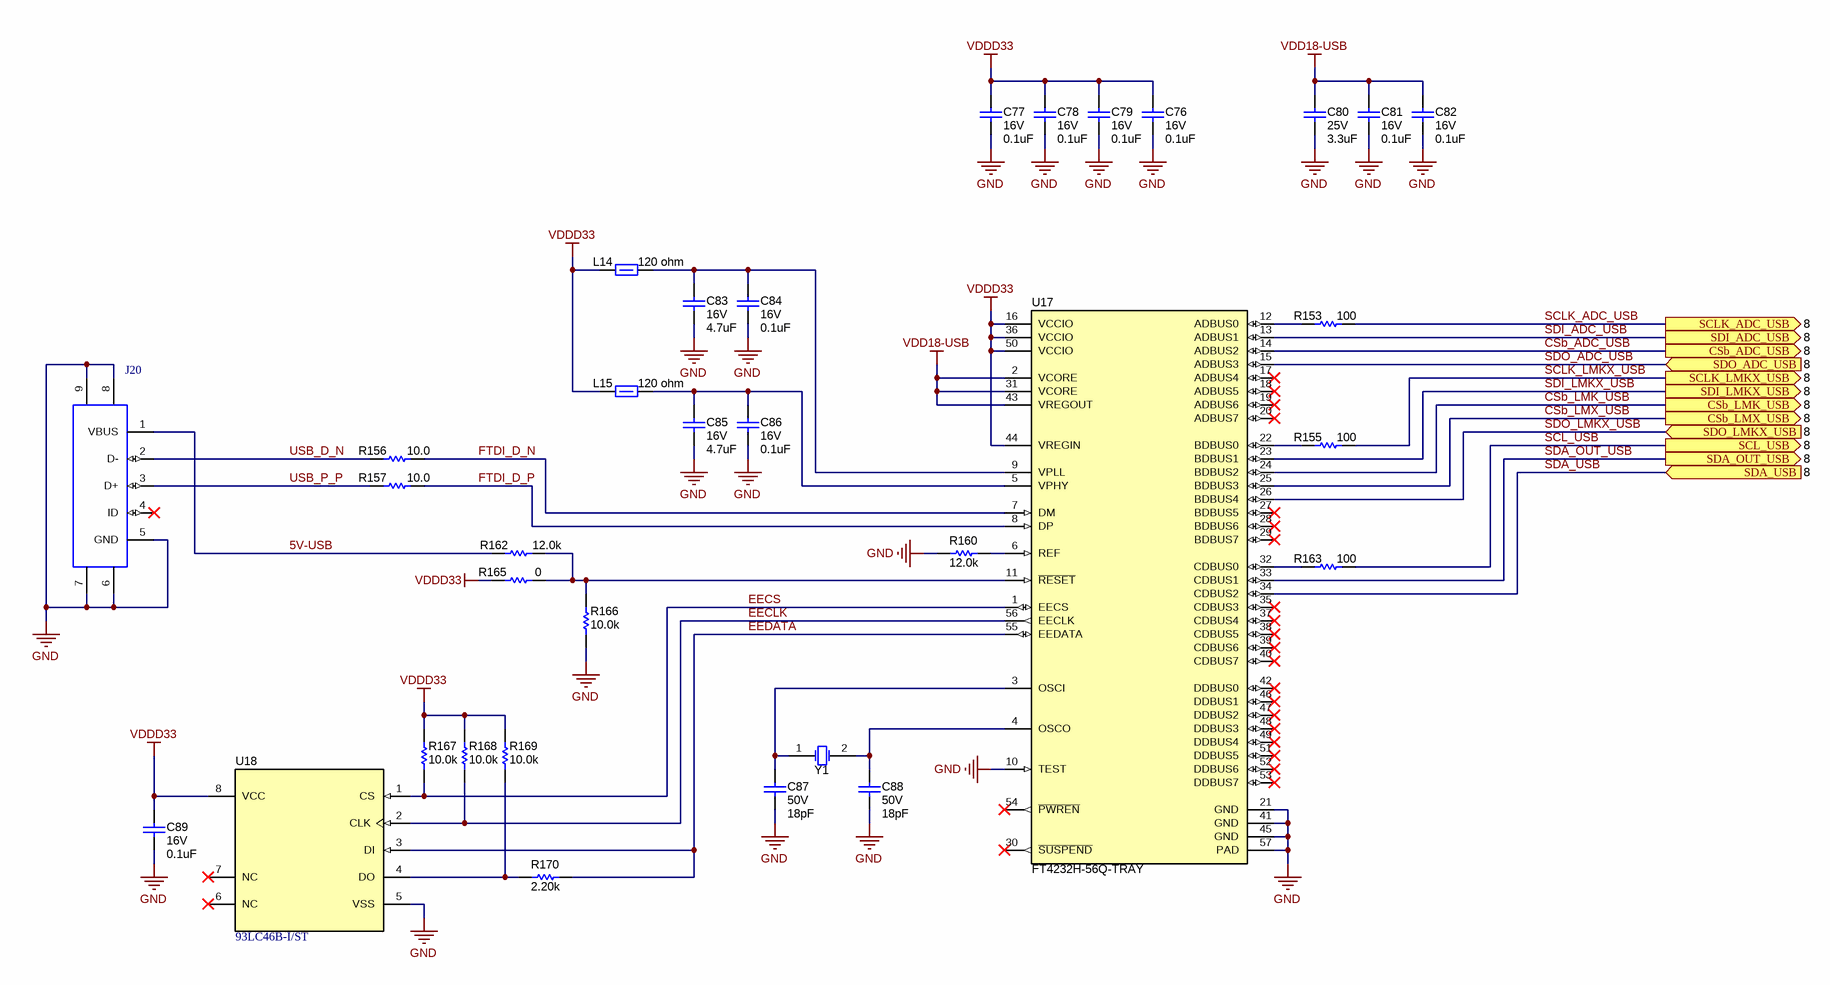
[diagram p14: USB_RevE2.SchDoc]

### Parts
C76  VDC_V: 16V  ValueDisplayed: 0.1uF  [0201L]  (hidden comment: GRM033Z71C104KE14D)
C77  VDC_V: 16V  ValueDisplayed: 0.1uF  [0201L]  (hidden comment: GRM033Z71C104KE14D)
C78  VDC_V: 16V  ValueDisplayed: 0.1uF  [0201L]  (hidden comment: GRM033Z71C104KE14D)
C79  VDC_V: 16V  ValueDisplayed: 0.1uF  [0201L]  (hidden comment: GRM033Z71C104KE14D)
C80  VDC_V: 25V  ValueDisplayed: 3.3uF  [0603]  (hidden comment: C1608X5R1E335K080AC)
C81  VDC_V: 16V  ValueDisplayed: 0.1uF  [0201L]  (hidden comment: GRM033Z71C104KE14D)
C82  VDC_V: 16V  ValueDisplayed: 0.1uF  [0201L]  (hidden comment: GRM033Z71C104KE14D)
C83  VDC_V: 16V  ValueDisplayed: 4.7uF  [0603]  (hidden comment: GRM188Z71C475KE21D)
C84  VDC_V: 16V  ValueDisplayed: 0.1uF  [0201L]  (hidden comment: GRM033Z71C104KE14D)
C85  VDC_V: 16V  ValueDisplayed: 4.7uF  [0603]  (hidden comment: GRM188Z71C475KE21D)
C86  VDC_V: 16V  ValueDisplayed: 0.1uF  [0201L]  (hidden comment: GRM033Z71C104KE14D)
C87  VDC_V: 50V  ValueDisplayed: 18pF  [0402L]  (hidden comment: C1005C0G1H180J050BA)
C88  VDC_V: 50V  ValueDisplayed: 18pF  [0402L]  (hidden comment: C1005C0G1H180J050BA)
C89  VDC_V: 16V  ValueDisplayed: 0.1uF  [0201L]  (hidden comment: GRM033Z71C104KE14D)
J20  1734035-2  [CONN_USB-Mini-B-1734035-2]  (value not drawn)
L14  ValueDisplayed: 120 ohm  [0402]  (hidden comment: 74279271)
L15  ValueDisplayed: 120 ohm  [0402]  (hidden comment: 74279271)
R153  ValueDisplayed: 100  [0201L]  (hidden comment: RC0201FR-7D100RL)
R155  ValueDisplayed: 100  [0201L]  (hidden comment: RC0201FR-7D100RL)
R156  ValueDisplayed: 10.0  [0201L]  (hidden comment: RC0201FR-7D10RL)
R157  ValueDisplayed: 10.0  [0201L]  (hidden comment: RC0201FR-7D10RL)
R160  ValueDisplayed: 12.0k  [0201L]  (hidden comment: RC0201FR-7D12KL)
R162  ValueDisplayed: 12.0k  [0201L]  (hidden comment: RC0201FR-7D12KL)
R163  ValueDisplayed: 100  [0201L]  (hidden comment: RC0201FR-7D100RL)
R165  ValueDisplayed: 0  [0201L]  (hidden comment: CRCW02010000Z0ED)
R166  ValueDisplayed: 10.0k  [0201L]  (hidden comment: RC0201FR-7D10KL)
R167  ValueDisplayed: 10.0k  [0201L]  (hidden comment: RC0201FR-7D10KL)
R168  ValueDisplayed: 10.0k  [0201L]  (hidden comment: RC0201FR-7D10KL)
R169  ValueDisplayed: 10.0k  [0201L]  (hidden comment: RC0201FR-7D10KL)
R170  ValueDisplayed: 2.20k  [0201L]  (hidden comment: RC0201FR-7D2K2L)
U17  FT4232H-56Q-TRAY  [VQFN-56]
U18  93LC46B-I/ST  [TSSOP-8]
Y1  ABM3-12.000MHZ-D2Y-T  [XTAL_ABM3]  (value not drawn)

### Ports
CSb_ADC_USB (out, see 8), CSb_LMK_USB (out, see 8), CSb_LMX_USB (out, see 8), SCL_USB (out, see 8), SCLK_ADC_USB (out, see 8), SCLK_LMKX_USB (out, see 8), SDA_OUT_USB (out, see 8), SDA_USB (in, see 8), SDI_ADC_USB (out, see 8), SDI_LMKX_USB (out, see 8), SDO_ADC_USB (in, see 8), SDO_LMKX_USB (in, see 8)

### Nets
GND: C76.1 C77.1 C78.1 C79.1 C80.2 C81.1 C82.1 C83.2 C84.1 C85.2 C86.1 C87.2 C88.2 C89.1 J20.5(GND) J20.6 J20.7 J20.8 J20.9 R160.1 R166.2 U17.10(TEST) U17.21(GND) U17.41(GND) U17.45(GND) U17.57(PAD) U18.5(VSS)
VDD18-USB: C80.1 C81.2 C82.2 U17.2(VCORE) U17.31(VCORE) U17.43(VREGOUT)
VDDD33: C76.2 C77.2 C78.2 C79.2 C89.2 L14.1 L15.1 R165.1 R167.2 R168.2 R169.2 U17.16(VCCIO) U17.36(VCCIO) U17.44(VREGIN) U17.50(VCCIO) U18.8(VCC)
5V-USB: J20.1(VBUS) R162.1
CSb_ADC_USB: U17.14(ADBUS2) ; port CSb_ADC_USB
CSb_LMK_USB: U17.24(BDBUS2) ; port CSb_LMK_USB
CSb_LMX_USB: U17.25(BDBUS3) ; port CSb_LMX_USB
EECLK: R168.1 U17.56(EECLK) U18.2(CLK)
EECS: R167.1 U17.1(EECS) U18.1(CS)
EEDATA: R170.2 U17.55(EEDATA) U18.3(DI)
FTDI_D_N: R156.2 U17.7(DM)
FTDI_D_P: R157.2 U17.8(DP)
SCL_USB: R163.2 ; port SCL_USB
SCLK_ADC_USB: R153.2 ; port SCLK_ADC_USB
SCLK_LMKX_USB: R155.2 ; port SCLK_LMKX_USB
SDA_OUT_USB: U17.33(CDBUS1) ; port SDA_OUT_USB
SDA_USB: U17.34(CDBUS2) ; port SDA_USB
SDI_ADC_USB: U17.13(ADBUS1) ; port SDI_ADC_USB
SDI_LMKX_USB: U17.23(BDBUS1) ; port SDI_LMKX_USB
SDO_ADC_USB: U17.15(ADBUS3) ; port SDO_ADC_USB
SDO_LMKX_USB: U17.26(BDBUS4) ; port SDO_LMKX_USB
USB_D_N: J20.2(D-) R156.1
USB_P_P: J20.3(D+) R157.1
NetC83_1: C83.1 C84.2 L14.2 U17.9(VPLL)
NetC85_1: C85.1 C86.2 L15.2 U17.5(VPHY)
NetC87_1: C87.1 U17.3(OSCI) Y1.1(OSC1)
NetC88_1: C88.1 U17.4(OSCO) Y1.2(OSC2)
NetR153_1: R153.1 U17.12(ADBUS0)
NetR155_1: R155.1 U17.22(BDBUS0)
NetR160_2: R160.2 U17.6(REF)
NetR162_2: R162.2 R165.2 R166.1 U17.11(~{RESET})
NetR163_1: R163.1 U17.32(CDBUS0)
NetR169_1: R169.1 R170.1 U18.4(DO)

Not connected (* = marked no-connect by the designer): J20 4(ID)*; U17 17(ADBUS4)* 18(ADBUS5)* 19(ADBUS6)* 20(ADBUS7)* 27(BDBUS5)* 28(BDBUS6)* 29(BDBUS7)* 30(~{SUSPEND})* 35(CDBUS3)* 37(CDBUS4)* 38(CDBUS5)* 39(CDBUS6)* 40(CDBUS7)* 42(DDBUS0)* 46(DDBUS1)* 47(DDBUS2)* 48(DDBUS3)* 49(DDBUS4)* 51(DDBUS5)* 52(DDBUS6)* 53(DDBUS7)* 54(~{PWREN})*; U18 6(NC)* 7(NC)*

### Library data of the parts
C76-C79 C81 C82 C84 C86 C89 = CMP-0064970-1: CAP, CERM, 0.1 uF, 16 V,+/- 10%, X7R, 0201; Manufacturer: MuRata; TaMin_C: -55°C; Polarized: N; SizeAreaWB_mm2: 2.08; Value1: Unknown; U/M: EA; Value: 0.1uF; TaMax_C: 125°C; SizeZ_mm: 0.26; SizeX_mm: 0.6; SizeY_mm: 0.3; Cap_Case: 0201; SizeArea_mm2: 0.18; Cap_F: 100nF; AEC Category: Q200
C80 = CMP-0007008-5: CAP, CERM, 3.3 uF, 25 V, +/- 10%, X5R, 0603; Manufacturer: TDK; TaMin_C: -55°C; Polarized: N; SizeAreaWB_mm2: 4.68; Value1: Unknown; U/M: EA; Value: 3.3uF; TaMax_C: 85°C; SizeZ_mm: 1; SizeX_mm: 1.6; SizeY_mm: 0.8; SizeArea_mm2: 1.28; Cap_F: 3.3µF; AEC Category: Q200
C83 C85 = CMP-0064936-4: as C116 on sheet Power2_RevE2
C87 C88 = CMP-0006247-2: CAP, CERM, 18 pF, 50 V, +/- 5%, C0G/NP0, 0402; Manufacturer: TDK; TaMin_C: -55°C; Polarized: N; SizeAreaWB_mm2: 3; Value1: Unknown; U/M: EA; Value: 18pF; TaMax_C: 125°C; SizeZ_mm: 0.6; SizeX_mm: 1; SizeY_mm: 0.5; Cap_Case: 0402; AEC Category: Q200
J20 = CMP-0054920-2: Connector, Receptacle, Mini-USB Type B, R/A, Top Mount SMT; Manufacturer: TE Connectivity; Green_Lifecycle: Active; Gender: Female; Green_REACh: Incomplete; CompType: USB
L14 L15 = CMP-0003214-1: Ferrite Bead, 120 ohm @ 100 MHz, 0.5 A, 0402; Manufacturer: Wurth Elektronik; Ztyp@1GHz_Ohm: 175.42; ZTyp@100MHz_Ohm: 120; SizeAreaWB_mm2: 3; DCR_ohm: 2d; Value1: 0.2 ohm; Value: 120 ohm; Imax_A: 5dA; SizeZ_mm: 0.6; SizeX_mm: 1; SizeY_mm: 0.5; Value2: 0.5A
R153 R155 R163 = CMP-0027944-1: RES, 100, 1%, 0.05 W, 0201; Manufacturer: Yageo America; Power_W: 50mW; TempCo: 200 ppm/C; Value_Code: 100R; U/M: EA; Value: 100; EIA_Code: E96; SizeX_mm: 0.6; SizeY_mm: 0.3; SizeZ_mm: 0.26; Value2: 0.05W; SizeArea_mm2: 0.18; AEC Qualified: N; VDC_V: 25V; AEC Category: Q200
R156 R157 = CMP-0027946-1: RES, 10.0, 1%, 0.05 W, 0201; Manufacturer: Yageo America; Power_W: 50mW; TempCo: 350 ppm/C; Value_Code: 10R0; U/M: EA; Value: 10.0; EIA_Code: E96; Res_ohm: 10; SizeX_mm: 0.6; SizeY_mm: 0.3; SizeZ_mm: 0.26; Value2: 0.05W; SizeArea_mm2: 0.18; AEC Qualified: N; VDC_V: 25V; AEC Category: Q200
R160 = CMP-0027954-1: RES, 12.0 k, 1%, 0.05 W, 0201; Manufacturer: Yageo America; Power_W: 50mW; TempCo: 200 ppm/C; Value_Code: 12k0; U/M: EA; Value: 12.0k; Res_ohm: 12k; SizeX_mm: 0.6; SizeY_mm: 0.3; SizeZ_mm: 0.26; Value2: 0.05W; SizeArea_mm2: 0.18; CompType: Resistor; AEC Qualified: N; VDC_V: 25V; AEC Category: Q200
R162 = CMP-0027954-1: RES, 12.0 k, 1%, 0.05 W, 0201; Manufacturer: Yageo America; Power_W: 50mW; TempCo: 200 ppm/C; Value_Code: 12k0; U/M: EA; Value: 12.0k; Res_ohm: 12k; SizeX_mm: 0.6; SizeY_mm: 0.3; SizeZ_mm: 0.26; Value2: 0.05W; SizeArea_mm2: 0.18; AEC Qualified: N; VDC_V: 25V; AEC Category: Q200
R165 = CMP-0027008-4: as R98 on sheet Power2_RevE2
R166-R169 = CMP-0027945-1: RES, 10.0 k, 1%, 0.05 W, 0201; Manufacturer: Yageo America; Power_W: 50mW; TempCo: 200 ppm/C; Value_Code: 10k0; U/M: EA; Value: 10.0k; EIA_Code: E96; Res_ohm: 10k; SizeX_mm: 0.6; SizeY_mm: 0.3; SizeZ_mm: 0.26; Value2: 0.05W; SizeArea_mm2: 0.18; AEC Qualified: N; VDC_V: 25V; AEC Category: Q200
R170 = CMP-0027995-1: RES, 2.20 k, 1%, 0.05 W, 0201; Manufacturer: Yageo America; Power_W: 50mW; TempCo: 200 ppm/C; Value_Code: 2k20; U/M: EA; Value: 2.20k; Res_ohm: 2.2k; SizeX_mm: 0.6; SizeY_mm: 0.3; SizeZ_mm: 0.26; Value2: 0.05W; SizeArea_mm2: 0.18; AEC Qualified: N; VDC_V: 25V; AEC Category: Q200
U17 = CMP-0081661-1: Future Technology Devices International Ltd FT4232H Quad High Speed USB to Multipurpose UART/MPSSE IC, VQFN-56; Manufacturer: FTDI; SizeZ_mm: 1; SizeX_mm: 8; SizeArea_mm2: 64; SizeAreaWB_mm2: 100
U18 = CMP-0081524-1: 1K Microwire Compatible Serial EEPROM, TSSOP-8; Manufacturer: Microchip; SizeArea_mm2: 19.2; SizeAreaWB_mm2: 42; SizeY_mm: 3; SizeZ_mm: 1.2; SizeX_mm: 6.4
Y1 = CMP-0004616-3: Crystal, 12 MHz, 18 pF, SMD; Manufacturer: Abracon Corporation; TaMin_C: -40°C; Frequency Stability: +/-30ppm; Frequency_Fixed: 12MHz; TaMax_C: 85°C

## Sheet Balun Test RevE2.SchDoc
size 431 x 279 mm; Date: Not shown in title block; ApprovedBy: Not shown in title block; CheckedBy: Not shown in title block; Author: Not shown in title block; CompanyName: Not shown in title block; Engineer: Not shown in title block; Organization: Not shown in title block; Address1: Not shown in title block; Address2: Not shown in title block; Address3: Not shown in title block; Address4: Not shown in title block; DocumentNumber: 15; Revision: Use project parameter SCH_Rev; SheetNumber: 15; SheetTotal: 15; PageSetup: Record=PageOptions¦CenterHorizontal=True¦CenterVertical=True¦PrintScale=1.00¦XCorrection=1.00¦YCorrection=1.00¦PrintKind=0¦BorderSize=5000000¦LeftOffset=0¦BottomOffset=0¦Orientation=2¦PaperLength=1000¦PaperWidth=1000¦Scale=100¦PaperSource=15¦PrintQuality=600¦MediaType=1¦DitherType=10¦PaperKind=Letter¦PrintScaleMode=1
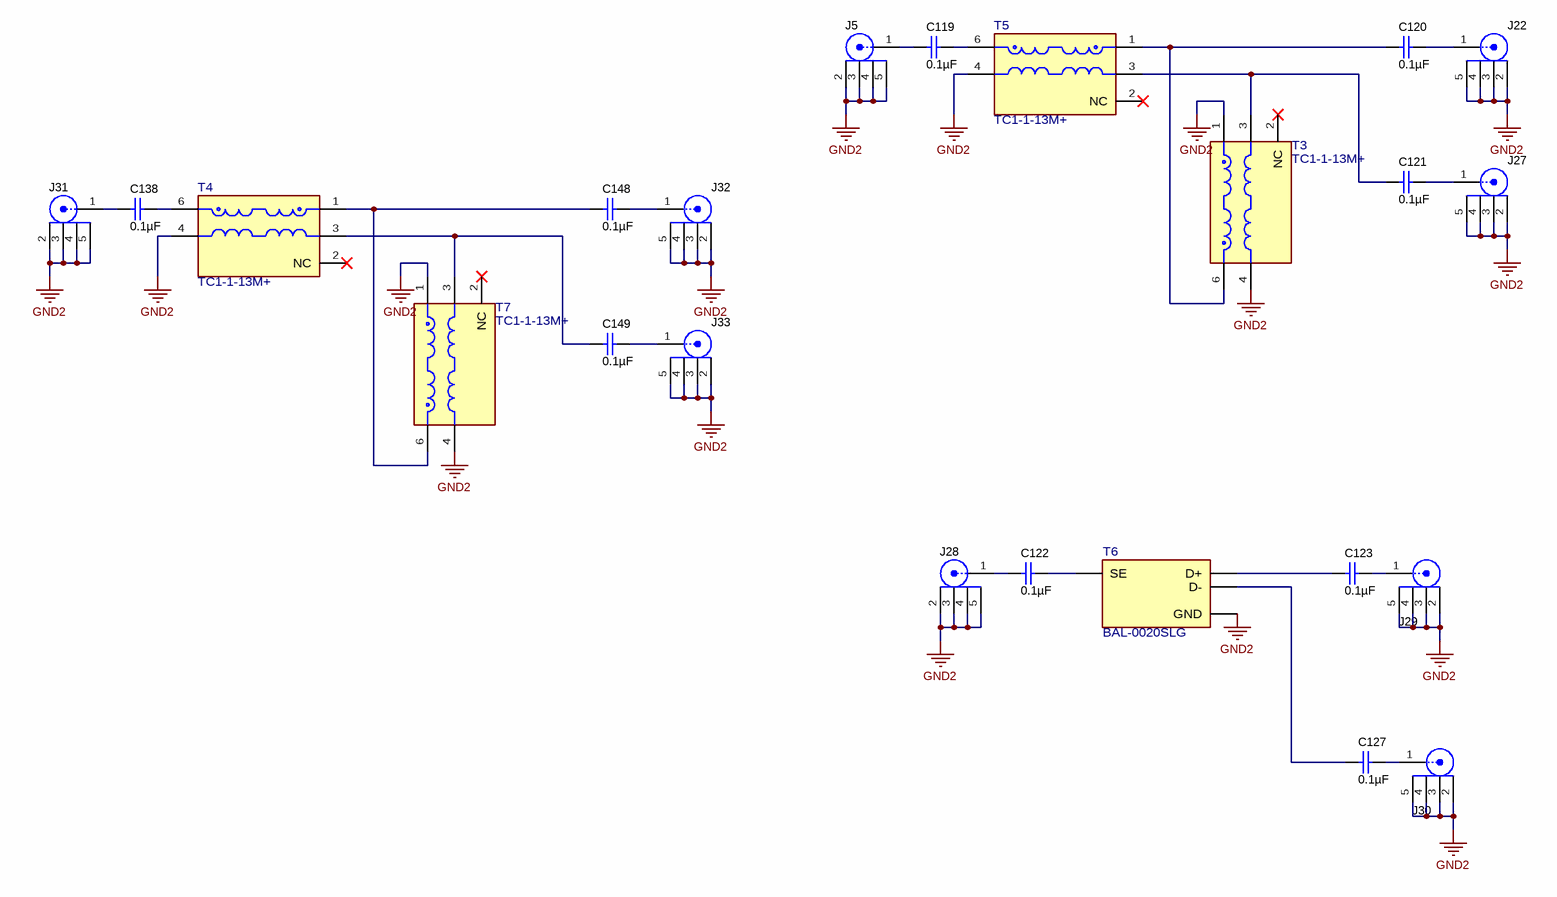
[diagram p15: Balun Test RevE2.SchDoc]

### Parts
C119  ValueDisplayed: 0.1µF  [0201_033]  (hidden comment: 0201BB104KW160)
C120  ValueDisplayed: 0.1µF  [0201_033]  (hidden comment: 0201BB104KW160)
C121  ValueDisplayed: 0.1µF  [0201_033]  (hidden comment: 0201BB104KW160)
C122  ValueDisplayed: 0.1µF  [0201_033]  (hidden comment: 0201BB104KW160)
C123  ValueDisplayed: 0.1µF  [0201_033]  (hidden comment: 0201BB104KW160)
C127  ValueDisplayed: 0.1µF  [0201_033]  (hidden comment: 0201BB104KW160)
C138  ValueDisplayed: 0.1µF  [0201_033]  (hidden comment: 0201BB104KW160)
C148  ValueDisplayed: 0.1µF  [0201_033]  (hidden comment: 0201BB104KW160)
C149  ValueDisplayed: 0.1µF  [0201_033]  (hidden comment: 0201BB104KW160)
J5  SASF546-P26-X1  [CONN_LTI_SASF546-P26-X1]  (value not drawn)
J22  SASF546-P26-X1  [CONN_LTI_SASF546-P26-X1]  (value not drawn)
J27  SASF546-P26-X1  [CONN_LTI_SASF546-P26-X1]  (value not drawn)
J28  SASF546-P26-X1  [CONN_LTI_SASF546-P26-X1]  (value not drawn)
J29  SASF546-P26-X1  [CONN_LTI_SASF546-P26-X1]  (value not drawn)
J30  SASF546-P26-X1  [CONN_LTI_SASF546-P26-X1]  (value not drawn)
J31  SASF546-P26-X1  [CONN_LTI_SASF546-P26-X1]  (value not drawn)
J32  SASF546-P26-X1  [CONN_LTI_SASF546-P26-X1]  (value not drawn)
J33  SASF546-P26-X1  [CONN_LTI_SASF546-P26-X1]  (value not drawn)
T3  TC1-1-13M+  [FP-TC1-1-13M+_SMT_3MM81_3MM81-MFG]
T4  TC1-1-13M+  [FP-TC1-1-13M+_SMT_3MM81_3MM81-MFG]
T5  TC1-1-13M+  [FP-TC1-1-13M+_SMT_3MM81_3MM81-MFG]
T6  BAL-0020SLG  [FP-BAL-0020SLG_SMT_BALUN_12MM70_5MM08-MFG]
T7  TC1-1-13M+  [FP-TC1-1-13M+_SMT_3MM81_3MM81-MFG]

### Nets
GND2: J5.2 J5.3 J5.4 J5.5 J22.2 J22.3 J22.4 J22.5 J27.2 J27.3 J27.4 J27.5 J28.2 J28.3 J28.4 J28.5 J29.2 J29.3 J29.4 J29.5 J30.2 J30.3 J30.4 J30.5 J31.2 J31.3 J31.4 J31.5 J32.2 J32.3 J32.4 J32.5 J33.2 J33.3 J33.4 J33.5 T3.1(SECONDARY_DOT) T3.4(PRIMARY) T4.4(PRIMARY) T5.4(PRIMARY) T6.4(GND) T7.1(SECONDARY_DOT) T7.4(PRIMARY)
NetC119_1: C119.1 T5.6(PRIMARY_DOT)
NetC119_2: C119.2 J5.1
NetC120_1: C120.1 J22.1
NetC120_2: C120.2 T3.6(PRIMARY_DOT) T5.1(SECONDARY_DOT)
NetC121_1: C121.1 J27.1
NetC121_2: C121.2 T3.3(SECONDARY) T5.3(SECONDARY)
NetC122_1: C122.1 T6.1(SE)
NetC122_2: C122.2 J28.1
NetC123_1: C123.1 T6.3(D+)
NetC123_2: C123.2 J29.1
NetC127_1: C127.1 T6.2(D-)
NetC127_2: C127.2 J30.1
NetC138_1: C138.1 T4.6(PRIMARY_DOT)
NetC138_2: C138.2 J31.1
NetC148_1: C148.1 J32.1
NetC148_2: C148.2 T4.1(SECONDARY_DOT) T7.6(PRIMARY_DOT)
NetC149_1: C149.1 J33.1
NetC149_2: C149.2 T4.3(SECONDARY) T7.3(SECONDARY)

Not connected (* = marked no-connect by the designer): T3 2(NC)*; T4 2(NC)*; T5 2(NC)*; T7 2(NC)*

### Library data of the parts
C119-C123 C127 C138 C148 C149 = CMP-0860981-1: CAP, CERM, 0.1 µF, 16 V,+/- 10%, X7R, 0201; Alternate Manufacturer: Murata; Manufacturer: Passive Plus; Alternate PartNumber: GRM033R60J104KE19D; Value: 0.1uF; Polarized: N; SizeY_mm: 0.3; TaMin_C: -55°C; U/M: EA; Cap_Case: 0201; AEC Category: Q200; SizeZ_mm: 0.33; Value2: 16V; SizeArea_mm2: 0.18; SizeX_mm: 0.6; Cap_F: 100nF; SizeAreaWB_mm2: 2.08; TaMax_C: 125°C
J5 J22 J27-J33 = CMP-0055826-1: Connector, SMA,Vertical, Thru hole w/SMT center pin; Manufacturer: Lighthorse Technologies; CT: TRUE; Green_REACh: Incomplete; CNHeader: FALSE; Green_Lifecycle: Not Set
T3-T5 T7 = CMP-0087865-1: RF Transformer Surface Mount 50Ω 4.5 to 3000 MHz; Manufacturer: Mini-Circuits; SizeZ_mm: 4.06mm; Ns1toNp: 1:1; AEC Qualified: No
T6 = CMP-0090705-1: 10 MHz to 20 GHz 1:2 Balun, Surface Mount; Manufacturer: Marki Microwave; Bandwidth: 19.99GHz; Filter Type: Band Pass; Frequency_Fixed: 0.01-20GHz; AEC Qualified: No; Insertion Loss: 7dB; SizeZ_mm: 2.79mm

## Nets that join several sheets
3.3V-LMX: Clocks3_RevE2 (16 pins), Power1_RevE2 (5 pins)
3p3VAMP: Analog_Frontend_RevE2 (R3.2 R4.2 R179.2), Power1_RevE2 (5 pins)
+3.3VA: Power1_RevE2 (18 pins), Power2_RevE2 (17 pins)
+3.3VCLK: Clocks_RevE2 (9 pins), Clocks2_RevE2 (8 pins), Power1_RevE2 (5 pins)
+7V: Power1_RevE2 (17 pins), Power2_RevE2 (30 pins)
FE_VDD: Analog_Frontend_RevE2 (FB1.1), Power2_RevE2 (C113.1 C114.1 FB4.2)
GND: ADC_Input_RevE2 (13 pins), ADC_Power_RevE2 (75 pins), ADC_RevE2 (16 pins), Analog_Frontend_RevE2 (18 pins), Clocks_RevE2 (38 pins), Clocks2_RevE2 (30 pins), Clocks3_RevE2 (33 pins), FMC_RevE2 (238 pins), GPIO_RevE2 (15 pins), GPIO2_RevE2 (52 pins), Misc_RevE2 (H1.1 H2.1 H3.1 H4.1), Power1_RevE2 (69 pins), Power2_RevE2 (109 pins), USB_RevE2 (27 pins)
VA11: ADC_Power_RevE2 (22 pins), Power2_RevE2 (5 pins)
VA19: ADC_Power_RevE2 (18 pins), Power2_RevE2 (5 pins)
VD11: ADC_Power_RevE2 (20 pins), Power2_RevE2 (6 pins)
VDDD33: ADC_RevE2 (8 pins), FMC_RevE2 (R217.1), GPIO_RevE2 (R177.2 U36.8), GPIO2_RevE2 (24 pins), Power1_RevE2 (5 pins), USB_RevE2 (16 pins)
VDDL19: Clocks2_RevE2 (R277.2), FMC_RevE2 (6 pins), GPIO_RevE2 (6 pins), GPIO2_RevE2 (22 pins), Power2_RevE2 (5 pins)
CALSTAT_ADC: ADC_RevE2 (U1.F7), GPIO_RevE2 (R219.2 TP15.1)
CALSTAT_FMC: FMC_RevE2 (J1.G28), GPIO_RevE2 (R219.1)
CALTRIG_ADC: ADC_RevE2 (U1.E7), GPIO_RevE2 (J18.2 R60.1 R69.2)
CALTRIG_FMC: FMC_RevE2 (J1.G27), GPIO_RevE2 (R60.2)
CLK0-500k: Power1_RevE2 (R127.2), Power2_RevE2 (U7.3)
CLK1-500k: Power1_RevE2 (R129.2), Power2_RevE2 (U9.3)
CLK3-500k: Power1_RevE2 (R233.2), Power2_RevE2 (U43.3)
CLK_ADC_LMX_N: ADC_RevE2 (C45.2), Clocks3_RevE2 (R253.1 U52.22)
CLK_ADC_LMX_P: ADC_RevE2 (C46.2), Clocks3_RevE2 (R252.1 U52.23)
CSb_ADC: ADC_RevE2 (U1.E8), GPIO2_RevE2 (U34.10)
CSb_ADC_FMC: FMC_RevE2 (J1.H34), GPIO2_RevE2 (R75.2 U13.3)
CSb_ADC_USB: GPIO2_RevE2 (R72.1), USB_RevE2 (U17.14)
CSb_LMK: Clocks_RevE2 (U6.18), GPIO2_RevE2 (U32.7)
CSb_LMK_FMC: FMC_RevE2 (J1.H35), GPIO2_RevE2 (R77.2 U14.1)
CSb_LMK_USB: GPIO2_RevE2 (R88.1), USB_RevE2 (U17.24)
CSb_LMX: Clocks3_RevE2 (U52.24), GPIO2_RevE2 (U32.10)
CSb_LMX_FMC: FMC_RevE2 (J1.H37), GPIO2_RevE2 (R78.2 U14.2)
CSb_LMX_USB: GPIO2_RevE2 (R106.1), USB_RevE2 (U17.25)
DA0_FMC_N: ADC_RevE2 (C14.1), FMC_RevE2 (J1.A11)
DA0_FMC_P: ADC_RevE2 (C13.1), FMC_RevE2 (J1.A10)
DA1_FMC_N: ADC_RevE2 (C16.1), FMC_RevE2 (J1.C7)
DA1_FMC_P: ADC_RevE2 (C15.1), FMC_RevE2 (J1.C6)
DA2_FMC_N: ADC_RevE2 (C18.1), FMC_RevE2 (J1.A7)
DA2_FMC_P: ADC_RevE2 (C17.1), FMC_RevE2 (J1.A6)
DA3_FMC_N: ADC_RevE2 (C20.1), FMC_RevE2 (J1.A3)
DA3_FMC_P: ADC_RevE2 (C19.1), FMC_RevE2 (J1.A2)
DA4_FMC_N: ADC_RevE2 (C22.1), FMC_RevE2 (J1.Z13)
DA4_FMC_P: ADC_RevE2 (C21.1), FMC_RevE2 (J1.Z12)
DA5_FMC_N: ADC_RevE2 (C24.1), FMC_RevE2 (J1.Y11)
DA5_FMC_P: ADC_RevE2 (C23.1), FMC_RevE2 (J1.Y10)
DA6_FMC_N: ADC_RevE2 (C26.1), FMC_RevE2 (J1.B9)
DA6_FMC_P: ADC_RevE2 (C25.1), FMC_RevE2 (J1.B8)
DA7_FMC_N: ADC_RevE2 (C28.1), FMC_RevE2 (J1.B5)
DA7_FMC_P: ADC_RevE2 (C27.1), FMC_RevE2 (J1.B4)
DB0_FMC_N: ADC_RevE2 (C30.1), FMC_RevE2 (J1.B12)
DB0_FMC_P: ADC_RevE2 (C29.1), FMC_RevE2 (J1.B13)
DB1_FMC_N: ADC_RevE2 (C32.1), FMC_RevE2 (J1.A14)
DB1_FMC_P: ADC_RevE2 (C31.1), FMC_RevE2 (J1.A15)
DB2_FMC_N: ADC_RevE2 (C34.1), FMC_RevE2 (J1.B16)
DB2_FMC_P: ADC_RevE2 (C33.1), FMC_RevE2 (J1.B17)
DB3_FMC_N: ADC_RevE2 (C36.1), FMC_RevE2 (J1.A18)
DB3_FMC_P: ADC_RevE2 (C35.1), FMC_RevE2 (J1.A19)
DB4_FMC_N: ADC_RevE2 (C38.1), FMC_RevE2 (J1.Y14)
DB4_FMC_P: ADC_RevE2 (C37.1), FMC_RevE2 (J1.Y15)
DB5_FMC_N: ADC_RevE2 (C40.1), FMC_RevE2 (J1.Z16)
DB5_FMC_P: ADC_RevE2 (C39.1), FMC_RevE2 (J1.Z17)
DB6_FMC_N: ADC_RevE2 (C42.1), FMC_RevE2 (J1.Y18)
DB6_FMC_P: ADC_RevE2 (C41.1), FMC_RevE2 (J1.Y19)
DB7_FMC_N: ADC_RevE2 (C44.1), FMC_RevE2 (J1.Y22)
DB7_FMC_P: ADC_RevE2 (C43.1), FMC_RevE2 (J1.Y23)
FGPA_GBTCLK5_FMC_N: Clocks_RevE2 (R44.2), FMC_RevE2 (J1.Z21)
FGPA_GBTCLK5_FMC_P: Clocks_RevE2 (R42.2), FMC_RevE2 (J1.Z20)
FPGA_CLKA_FMC_N: Clocks_RevE2 (R63.2), FMC_RevE2 (J1.L25)
FPGA_CLKA_FMC_P: Clocks_RevE2 (R62.2), FMC_RevE2 (J1.L24)
FPGA_CLKB_FMC_N: Clocks_RevE2 (R40.2), FMC_RevE2 (J1.G7)
FPGA_CLKB_FMC_P: Clocks_RevE2 (R37.2), FMC_RevE2 (J1.G6)
FPGA_GBTCLK0_FMC_N: Clocks_RevE2 (R227.2), FMC_RevE2 (J1.D5)
FPGA_GBTCLK0_FMC_P: Clocks_RevE2 (R226.2), FMC_RevE2 (J1.D4)
FPGA_GBTCLK1_FMC_N: Clocks_RevE2 (R41.2), FMC_RevE2 (J1.B21)
FPGA_GBTCLK1_FMC_P: Clocks_RevE2 (R38.2), FMC_RevE2 (J1.B20)
FPGA_SYSREF_FMC_N: Clocks_RevE2 (R53.2), FMC_RevE2 (J1.G10)
FPGA_SYSREF_FMC_P: Clocks_RevE2 (R51.2), FMC_RevE2 (J1.G9)
INA_ADC_N: ADC_RevE2 (U1.A5), Analog_Frontend_RevE2 (R183.2)
INA_ADC_P: ADC_RevE2 (U1.A4), Analog_Frontend_RevE2 (R188.2)
INB_ADC_N: ADC_Input_RevE2 (R15.2), ADC_RevE2 (U1.M5)
INB_ADC_P: ADC_Input_RevE2 (R11.2), ADC_RevE2 (U1.M4)
LMK_REF_N: Clocks_RevE2 (C50.2 R451.1), Clocks2_RevE2 (C508.1)
LMK_REF_P: Clocks_RevE2 (C49.2 R451.2), Clocks2_RevE2 (C507.1)
LMX_REF_N: Clocks2_RevE2 (C506.1), Clocks3_RevE2 (C347.2 R265.1)
LMX_REF_P: Clocks2_RevE2 (C505.1), Clocks3_RevE2 (C346.2 R265.2)
LMX_SYNC: Clocks_RevE2 (U49.7), Clocks3_RevE2 (U52.5)
LMX_SYSREFREQ: Clocks_RevE2 (U49.6), Clocks3_RevE2 (U52.28)
NCOA0_ADC: ADC_RevE2 (U1.C7), GPIO_RevE2 (J23.1 R83.1 R84.2)
NCOA0_FMC: FMC_RevE2 (J1.H25), GPIO_RevE2 (R83.2)
NCOA1_ADC: ADC_RevE2 (U1.D7), GPIO_RevE2 (J23.3 R87.1 R89.2)
NCOA1_FMC: FMC_RevE2 (J1.H26), GPIO_RevE2 (R87.2)
NCOB0_ADC: ADC_RevE2 (U1.K7), GPIO_RevE2 (J23.5 R91.1 R108.2)
NCOB0_FMC: FMC_RevE2 (J1.H28), GPIO_RevE2 (R91.2)
NCOB1_ADC: ADC_RevE2 (U1.J7), GPIO_RevE2 (J23.7 R109.1 R147.2)
NCOB1_FMC: FMC_RevE2 (J1.H29), GPIO_RevE2 (R109.2)
ORA0_ADC: ADC_RevE2 (U1.C8), GPIO_RevE2 (D4.2 R33.2 TP8.1)
ORA0_FMC: FMC_RevE2 (J1.D26), GPIO_RevE2 (R33.1)
ORA1_ADC: ADC_RevE2 (U1.D8), GPIO_RevE2 (R36.2 TP12.1)
ORA1_FMC: FMC_RevE2 (J1.D27), GPIO_RevE2 (R36.1)
ORB0_ADC: ADC_RevE2 (U1.K8), GPIO_RevE2 (D5.2 R71.2 TP13.1)
ORB0_FMC: FMC_RevE2 (J1.C26), GPIO_RevE2 (R71.1)
ORB1_ADC: ADC_RevE2 (U1.J8), GPIO_RevE2 (R82.2 TP14.1)
ORB1_FMC: FMC_RevE2 (J1.C27), GPIO_RevE2 (R82.1)
PD_ADC: ADC_RevE2 (U1.K6), GPIO_RevE2 (J12.2 R27.1 R28.2)
PD_FMC: FMC_RevE2 (J1.G30), GPIO_RevE2 (R27.2)
REF_SEL_FMC: Clocks2_RevE2 (R278.2), FMC_RevE2 (J1.G12)
SCL2_FMC: FMC_RevE2 (J1.G13), GPIO2_RevE2 (R80.2 U15.1)
SCL_FMC: ADC_RevE2 (U4.13), Analog_Frontend_RevE2 (R195.2), Clocks2_RevE2 (U51.8), FMC_RevE2 (R807.1), GPIO2_RevE2 (R804.2 R805.1)
SCL_USB: GPIO2_RevE2 (R149.1), USB_RevE2 (R163.2)
SCLK_ADC: ADC_RevE2 (U1.F8), GPIO2_RevE2 (U34.12)
SCLK_ADC_USB: GPIO2_RevE2 (R54.1), USB_RevE2 (R153.2)
SCLK_FMC: FMC_RevE2 (J1.G31), GPIO2_RevE2 (R73.2 U13.1)
SCLK_LMKX: Clocks_RevE2 (U6.19), Clocks3_RevE2 (U52.16), GPIO2_RevE2 (U32.2)
SCLK_LMKX_USB: GPIO2_RevE2 (R79.1), USB_RevE2 (R155.2)
SDA2_I_FMC: FMC_RevE2 (J1.G37), GPIO2_RevE2 (R207.2)
SDA2_O_FMC: FMC_RevE2 (J1.H38), GPIO2_RevE2 (R81.2 U15.2)
SDA_FMC: ADC_RevE2 (U4.12), Analog_Frontend_RevE2 (R197.2), Clocks2_RevE2 (U51.7), FMC_RevE2 (R808.1), GPIO2_RevE2 (R851.1 R852.2)
SDA_OUT_USB: GPIO2_RevE2 (R150.1), USB_RevE2 (U17.33)
SDA_USB: GPIO2_RevE2 (R151.1), USB_RevE2 (U17.34)
SDI_ADC: ADC_RevE2 (U1.G8), GPIO2_RevE2 (U34.11)
SDI_ADC_USB: GPIO2_RevE2 (R59.1), USB_RevE2 (U17.13)
SDI_FMC: FMC_RevE2 (J1.G33), GPIO2_RevE2 (R74.2 U13.2)
SDI_LMKX: Clocks_RevE2 (U6.20), Clocks3_RevE2 (U52.17), GPIO2_RevE2 (U32.5)
SDI_LMKX_USB: GPIO2_RevE2 (R85.1), USB_RevE2 (U17.23)
SDO_ADC: ADC_RevE2 (U1.H8), GPIO2_RevE2 (U34.9)
SDO_ADC_FMC: FMC_RevE2 (J1.G34), GPIO2_RevE2 (R178.2)
SDO_ADC_USB: GPIO2_RevE2 (R76.1), USB_RevE2 (U17.15)
SDO_LMKX: Clocks_RevE2 (R34.2), Clocks3_RevE2 (R70.1), GPIO2_RevE2 (U33.2)
SDO_LMKX_FMC: FMC_RevE2 (J1.G36), GPIO2_RevE2 (U14.3)
SDO_LMKX_USB: GPIO2_RevE2 (R148.1), USB_RevE2 (U17.26)
SYNCB_ADC: ADC_RevE2 (U1.C2), FMC_RevE2 (U59.4)
SYSREF_ADC_LMK_N: ADC_RevE2 (C61.2), Clocks_RevE2 (R49.2 R360.2)
SYSREF_ADC_LMK_P: ADC_RevE2 (C60.2), Clocks_RevE2 (R39.2 R359.2)
SYSREF_ADC_LMX_N: ADC_RevE2 (C306.2), Clocks3_RevE2 (R258.1 U52.18)
SYSREF_ADC_LMX_P: ADC_RevE2 (C52.2), Clocks3_RevE2 (R259.1 U52.19)

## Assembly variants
Onboard clock: not fitted C2 C3 C60 C61 C98 C106 J15 J16 R1 R7 R8 R9 R16 R27 R33 R36 R45 R46 R47 R48 R50 R52 R55 R56 R60 R64 R65 R71 R82 R83 R87 R91 R95 R100 R101 R102 R109 R112 R120 R123 R126 R127 R128 R129 R140 R141 R143 R146 R162 R166 R172 R215 R219 R230 R233 R238 R239 R241 R256 R278 R280 R359 R360 R807 R808
External clock: not fitted C52 C98 C106 C306 J15 J16 R1 R8 R9 R16 R27 R33 R36 R45 R46 R47 R48 R50 R52 R55 R56 R60 R64 R65 R71 R82 R83 R87 R91 R95 R100 R101 R102 R109 R112 R120 R123 R126 R127 R128 R129 R140 R141 R143 R146 R162 R166 R171 R172 R174 R215 R219 R230 R233 R238 R239 R241 R256 R278 R280 R359 R360 R807 R808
